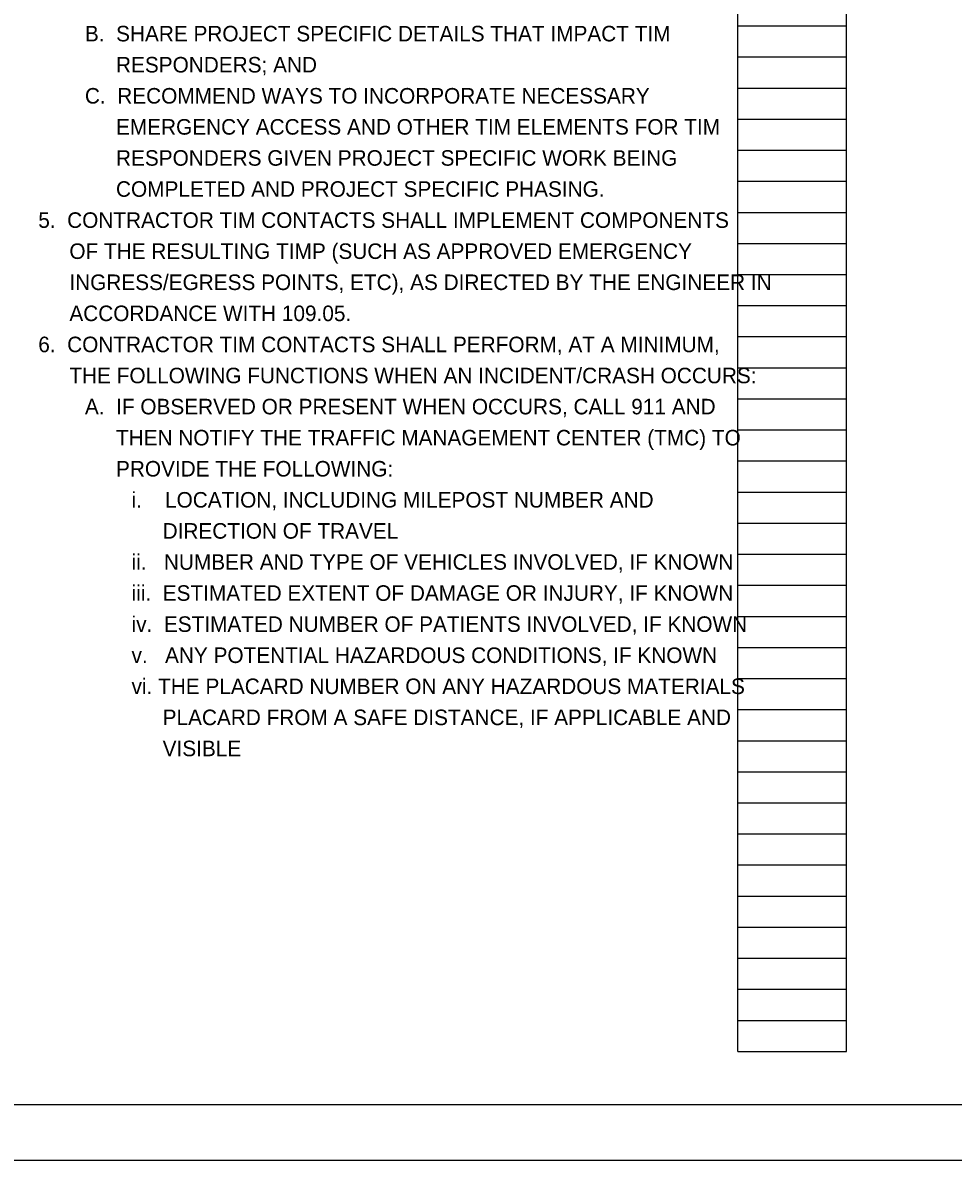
# Model space of a CAD drawing. Extents: x 0 to 69.3, y 0 to 22.
# Drawn here: x 17.24 to 25.62, y 0 to 10.25 of the extents above; entities that cross this region are included whole.
import ezdxf

# ---------------------------------------------------------------- set-up
doc = ezdxf.new("R2010")
doc.units = 0
for name, color, linetype in [('SH_Border', 7, 'Continuous'), ('SH_Cut_Line', 7, 'Continuous'), ('SH_Data', 7, 'Continuous'), ('SH_Text', 7, 'Continuous')]:
    doc.layers.add(name, color=color, linetype=linetype)

msp = doc.modelspace()

# ---------------------------------------------------------------- linework, layer by layer
at = {"layer": 'SH_Border'}
msp.add_lwpolyline([(1.5, 21.5), (33.5, 21.5), (33.5, 0.5), (1.5, 0.5)], close=True, dxfattribs=at)
at = {"layer": 'SH_Cut_Line'}
msp.add_lwpolyline([(0, 0), (34, 0), (34, 22), (0, 22)], close=True, dxfattribs=at)
at = {"layer": 'SH_Data'}
for p, q in [((23.68, 0.98), (23.68, 21.14)), ((24.66, 0.98), (24.66, 21.14)), ((23.68, 10.22), (24.66, 10.22)), ((23.68, 9.94), (24.66, 9.94)), ((23.68, 9.66), (24.66, 9.66)), ((23.68, 9.38), (24.66, 9.38)), ((23.68, 9.1), (24.66, 9.1)), ((23.68, 8.82), (24.66, 8.82)), ((23.68, 8.54), (24.66, 8.54)), ((23.68, 8.26), (24.66, 8.26)), ((23.68, 7.98), (24.66, 7.98)), ((23.68, 7.7), (24.66, 7.7)), ((23.68, 7.42), (24.66, 7.42)), ((23.68, 7.14), (24.66, 7.14)), ((23.68, 6.86), (24.66, 6.86)), ((23.68, 6.58), (24.66, 6.58)), ((23.68, 6.3), (24.66, 6.3)), ((23.68, 6.02), (24.66, 6.02)), ((23.68, 5.74), (24.66, 5.74)), ((23.68, 5.46), (24.66, 5.46)), ((23.68, 5.18), (24.66, 5.18)), ((23.68, 4.9), (24.66, 4.9)), ((23.68, 4.62), (24.66, 4.62)), ((23.68, 4.34), (24.66, 4.34)), ((23.68, 4.06), (24.66, 4.06)), ((23.68, 3.78), (24.66, 3.78)), ((23.68, 3.5), (24.66, 3.5)), ((23.68, 3.22), (24.66, 3.22)), ((23.68, 2.94), (24.66, 2.94)), ((23.68, 2.66), (24.66, 2.66)), ((23.68, 2.38), (24.66, 2.38)), ((23.68, 2.1), (24.66, 2.1)), ((23.68, 1.82), (24.66, 1.82)), ((23.68, 1.54), (24.66, 1.54)), ((23.68, 1.26), (24.66, 1.26)), ((23.68, 0.98), (24.66, 0.98))]:
    msp.add_line(p, q, dxfattribs=at)

# ---------------------------------------------------------------- texts
at = {"layer": 'SH_Text'}
for s, p in [('B.  SHARE PROJECT SPECIFIC DETAILS THAT IMPACT TIM ', (17.8, 10.08)), ('RESPONDERS; AND ', (18.08, 9.8)), ('C.  RECOMMEND WAYS TO INCORPORATE NECESSARY ', (17.8, 9.52)), ('EMERGENCY ACCESS AND OTHER TIM ELEMENTS FOR TIM ', (18.08, 9.24)), ('RESPONDERS GIVEN PROJECT SPECIFIC WORK BEING ', (18.08, 8.96)), ('COMPLETED AND PROJECT SPECIFIC PHASING. ', (18.08, 8.68)), ('5.  CONTRACTOR TIM CONTACTS SHALL IMPLEMENT COMPONENTS ', (17.38, 8.4)), ('OF THE RESULTING TIMP (SUCH AS APPROVED EMERGENCY ', (17.66, 8.12)), ('INGRESS/EGRESS POINTS, ETC), AS DIRECTED BY THE ENGINEER IN ', (17.66, 7.84)), ('ACCORDANCE WITH 109.05. ', (17.66, 7.56)), ('6.  CONTRACTOR TIM CONTACTS SHALL PERFORM, AT A MINIMUM, ', (17.38, 7.28)), ('THE FOLLOWING FUNCTIONS WHEN AN INCIDENT/CRASH OCCURS: ', (17.66, 7)), ('A.  IF OBSERVED OR PRESENT WHEN OCCURS, CALL 911 AND ', (17.8, 6.72)), ('THEN NOTIFY THE TRAFFIC MANAGEMENT CENTER (TMC) TO ', (18.08, 6.44)), ('PROVIDE THE FOLLOWING: ', (18.08, 6.16)), ('i.    LOCATION, INCLUDING MILEPOST NUMBER AND ', (18.22, 5.88)), ('DIRECTION OF TRAVEL', (18.5, 5.6)), ('ii.   NUMBER AND TYPE OF VEHICLES INVOLVED, IF KNOWN', (18.22, 5.32)), ('iii.  ESTIMATED EXTENT OF DAMAGE OR INJURY, IF KNOWN', (18.22, 5.04)), ('iv.  ESTIMATED NUMBER OF PATIENTS INVOLVED, IF KNOWN', (18.22, 4.76)), ('v.   ANY POTENTIAL HAZARDOUS CONDITIONS, IF KNOWN', (18.22, 4.48)), ('vi. THE PLACARD NUMBER ON ANY HAZARDOUS MATERIALS ', (18.22, 4.2)), ('PLACARD FROM A SAFE DISTANCE, IF APPLICABLE AND ', (18.5, 3.92)), ('VISIBLE', (18.5, 3.64))]:
    msp.add_text(s, height=0.14, dxfattribs=at).set_placement(p)

doc.saveas('drawing.dxf')
